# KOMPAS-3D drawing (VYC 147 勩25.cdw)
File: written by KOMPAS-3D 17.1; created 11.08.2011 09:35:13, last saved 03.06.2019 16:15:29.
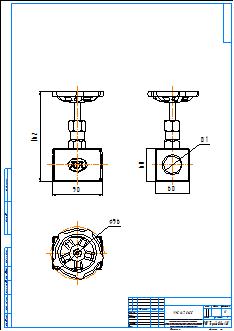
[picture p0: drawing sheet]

Sheet 1: A2, portrait

Title block, sheet 1: name: VYC 147 Ду25; material: Внимание! Данный продукт является объектом авторского права ООО «Торговый Дом АДЛ». / Запрещается изменение, копирование, распространение / (в том числе путем копирования на другие сайты и ресурсы в Интернете) / или любое иное использование информации и объектов без предварительного / согласия правообладателя (ООО «Торговый Дом АДЛ»).; scale: 1:1; sheets: 1; organisation: ООО "Торговый дом АДЛ"; sheet format: A2; stored path: \\adlc.lan\data\АДЛ_ПКД\3D-модели\Поставщики\VYC Industrial\VYC 147\KOMPAS 2D\VYC 147 Ду25.cdw

Views: Спереди 1, Проекционный вид 2, Проекционный вид 3
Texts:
  bsv
  adl
Dimensions and other numbers on the sheet: 90; 162; 60; 96; 1:1; 1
